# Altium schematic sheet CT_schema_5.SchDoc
size 218 x 258 mm
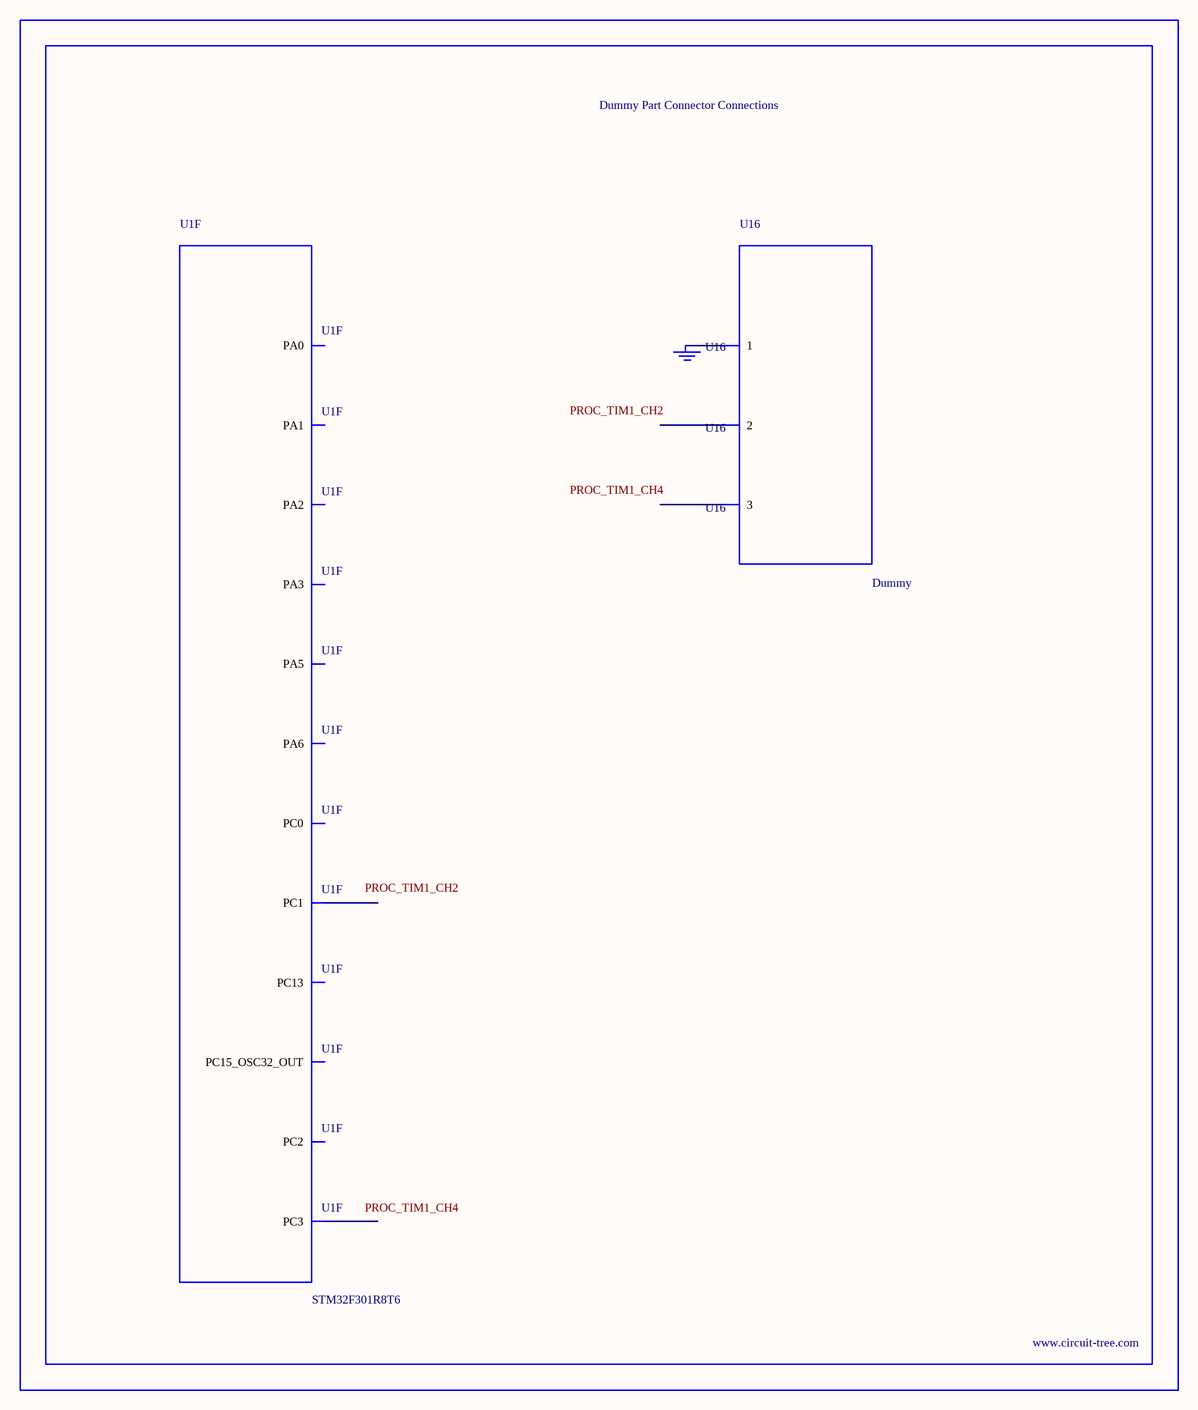
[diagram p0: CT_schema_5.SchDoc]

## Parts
BORDER4  (no value)
GND_INSTANCE_4_0  (no value)
U1  STM32F301R8T6  [LQFP64]  (part F of 6)
U16  Dummy  [DUMMY_PACKAGE_137]

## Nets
NetGND_INSTANCE_4_0_0: GND_INSTANCE_4_0.0(GND) U16.1

Not connected (* = marked no-connect by the designer): U1 2(PC13) 4(PC15_OSC32_OUT) 8(PC0) 9(PC1) 10(PC2) 11(PC3) 14(PA0) 15(PA1) 16(PA2) 17(PA3) 21(PA5) 22(PA6); U16 2 3

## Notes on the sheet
- Labels drawn without touching a wire or pin: PROC_TIM1_CH2, PROC_TIM1_CH4

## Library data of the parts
BORDER4 = BORDER_PAGE4
GND_INSTANCE_4_0 = GND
